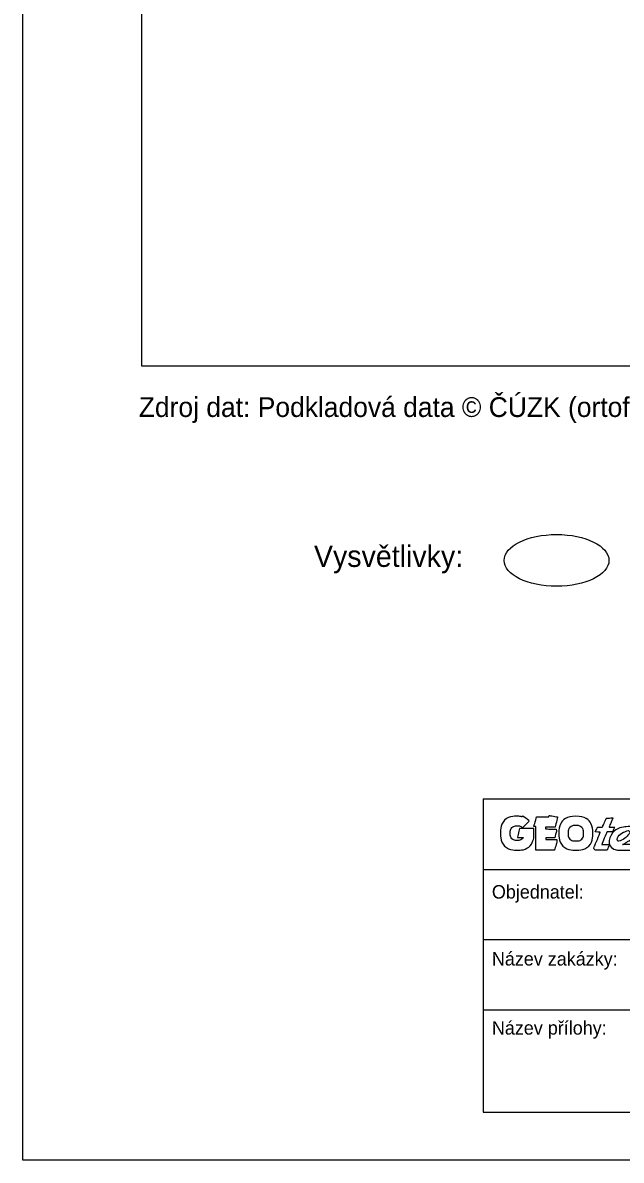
# Model space of a CAD drawing. Extents: x -600025 to -594775, y -1173009 to -1163890.
# Drawn here: x -600025 to -597810, y -1173009 to -1168801 of the extents above; entities that cross this region are included whole.
import ezdxf

# ---------------------------------------------------------------- set-up
doc = ezdxf.new("R2010")
doc.units = 0
doc.layers.add('razítko', color=7, linetype='Continuous')

msp = doc.modelspace()

# ---------------------------------------------------------------- linework, layer by layer
msp.add_lwpolyline([(-599584, -1165983.5), (-595112.9, -1165983.5), (-595112.9, -1170072.1), (-599584, -1170072.1)], close=True)
msp.add_ellipse((-598049.1, -1170790.4), major_axis=(193.8, 0), ratio=0.494798)
at = {"layer": 'razítko'}
for p, q in [((-598320.3, -1171672.8), (-598320.3, -1172831.8)), ((-598320.3, -1171673), (-595049.4, -1171673.3)), ((-598320.3, -1171673), (-595049.4, -1171673.3)), ((-598320.7, -1171933.3), (-595049.2, -1171933.5)), ((-598320.7, -1171933.3), (-595049.2, -1171933.5)), ((-598320.3, -1172193.1), (-595049.2, -1172193.4)), ((-598320.3, -1172193.1), (-595049.2, -1172193.4)), ((-598320.3, -1172453), (-595049.2, -1172453.2)), ((-598320.3, -1172453), (-595049.2, -1172453.2)), ((-598320.3, -1172832), (-595049.3, -1172832.3)), ((-598320.3, -1172832), (-595049.3, -1172832.3))]:
    msp.add_line(p, q, dxfattribs=at)
msp.add_lwpolyline([(-600024.6, -1165584.5), (-594774.6, -1165584.5), (-594774.6, -1173009.5), (-600024.6, -1173009.5)], close=True, dxfattribs=at)
for points in [[(-598150.1, -1171754.5), (-598150.1, -1171754.5), (-598175.1, -1171779.5), (-598175.1, -1171779.5), (-598175.1, -1171779.5), (-598180.1, -1171774.8), (-598186.8, -1171772.2), (-598193.7, -1171772.2), (-598193.7, -1171772.2), (-598208.6, -1171772.2), (-598220.8, -1171784.5), (-598220.8, -1171799.4), (-598220.8, -1171799.4), (-598220.8, -1171814.3), (-598208.6, -1171826.5), (-598193.7, -1171826.5), (-598193.7, -1171826.5), (-598184.8, -1171826.5), (-598176.6, -1171822.1), (-598171.6, -1171815), (-598171.6, -1171815), (-598171.6, -1171815), (-598193.3, -1171814.9), (-598193.3, -1171814.9), (-598193.3, -1171814.9), (-598193.3, -1171814.9), (-598186.4, -1171782), (-598186.4, -1171782), (-598186.4, -1171782), (-598186.4, -1171782), (-598132.7, -1171782.1), (-598132.7, -1171782.1), (-598132.7, -1171782.1), (-598132.7, -1171782.1), (-598132.8, -1171813.5), (-598132.8, -1171813.5), (-598132.8, -1171813.5), (-598139.2, -1171841.7), (-598164.6, -1171862), (-598193.7, -1171862), (-598193.7, -1171862), (-598228.2, -1171862), (-598256.3, -1171833.8), (-598256.3, -1171799.4), (-598256.3, -1171799.4), (-598256.3, -1171764.9), (-598228.2, -1171736.8), (-598193.7, -1171736.8), (-598193.7, -1171736.8), (-598188.3, -1171736.8), (-598182.7, -1171737.8), (-598177.5, -1171739), (-598177.5, -1171739), (-598177.5, -1171739), (-598174.8, -1171735.7), (-598174.8, -1171735.7), (-598174.8, -1171735.7), (-598174.8, -1171735.7), (-598150.1, -1171754.5), (-598150.1, -1171754.5)], [(-598125.5, -1171775.2), (-598125.5, -1171775.2), (-598125.5, -1171862.3), (-598125.5, -1171862.3), (-598125.5, -1171862.3), (-598125.5, -1171862.3), (-598056.6, -1171862.3), (-598056.6, -1171862.3), (-598056.6, -1171862.3), (-598056.6, -1171862.3), (-598047.9, -1171832.2), (-598047.9, -1171832.2), (-598047.9, -1171832.2), (-598047.9, -1171832.2), (-598047.9, -1171823.5), (-598047.9, -1171823.5), (-598047.9, -1171823.5), (-598047.9, -1171823.5), (-598089.1, -1171823.5), (-598089.1, -1171823.5), (-598089.1, -1171823.5), (-598089.1, -1171823.5), (-598089.1, -1171816.4), (-598089.1, -1171816.4), (-598089.1, -1171816.4), (-598089.1, -1171816.4), (-598055.8, -1171816.4), (-598055.8, -1171816.4), (-598055.8, -1171816.4), (-598055.8, -1171816.4), (-598049.5, -1171792.6), (-598049.5, -1171792.6), (-598049.5, -1171792.6), (-598049.5, -1171792.6), (-598050.3, -1171784.7), (-598050.3, -1171784.7), (-598050.3, -1171784.7), (-598050.3, -1171784.7), (-598089.9, -1171783.9), (-598089.9, -1171783.9), (-598089.9, -1171783.9), (-598089.9, -1171783.9), (-598089.9, -1171776.8), (-598089.9, -1171776.8), (-598089.9, -1171776.8), (-598089.9, -1171776.8), (-598054.2, -1171776.8), (-598054.2, -1171776.8), (-598054.2, -1171776.8), (-598054.2, -1171776.8), (-598045.5, -1171740.4), (-598045.5, -1171740.4), (-598045.5, -1171740.4), (-598045.5, -1171740.4), (-598045.5, -1171739.6), (-598045.5, -1171739.6), (-598045.5, -1171739.6), (-598045.5, -1171739.6), (-598076.4, -1171734), (-598076.4, -1171734), (-598076.4, -1171734), (-598076.4, -1171734), (-598078, -1171738.8), (-598078, -1171738.8), (-598078, -1171738.8), (-598078, -1171738.8), (-598123.1, -1171738.8), (-598123.1, -1171738.8), (-598123.1, -1171738.8), (-598123.1, -1171738.8), (-598133.4, -1171775.2), (-598133.4, -1171775.2), (-598133.4, -1171775.2), (-598133.4, -1171775.2), (-598125.5, -1171775.2), (-598125.5, -1171775.2)], [(-597977.8, -1171736.6), (-597943.2, -1171736.6), (-597915.1, -1171764.8), (-597915.1, -1171799.3), (-597915.1, -1171799.3), (-597915.1, -1171833.9), (-597943.2, -1171862.1), (-597977.8, -1171862.1), (-597977.8, -1171862.1), (-598012.3, -1171862.1), (-598040.5, -1171833.9), (-598040.5, -1171799.3), (-598040.5, -1171799.3), (-598040.5, -1171764.8), (-598012.3, -1171736.6), (-597977.8, -1171736.6)], [(-597853.8, -1171776.8), (-597853.8, -1171776.8), (-597855.4, -1171776.8), (-597853.8, -1171774.4), (-597853.8, -1171774.4), (-597853.8, -1171774.4), (-597841.1, -1171742.8), (-597841.1, -1171742.8), (-597841.1, -1171742.8), (-597841.1, -1171742.8), (-597864.9, -1171744.3), (-597864.9, -1171744.3), (-597864.9, -1171744.3), (-597864.9, -1171744.3), (-597877.6, -1171772.9), (-597877.6, -1171772.9), (-597877.6, -1171772.9), (-597879.2, -1171776.8), (-597881.5, -1171776.8), (-597882.3, -1171776.8), (-597882.3, -1171776.8), (-597882.3, -1171776.8), (-597897.4, -1171777.6), (-597897.4, -1171777.6), (-597897.4, -1171777.6), (-597897.4, -1171777.6), (-597906.1, -1171795), (-597906.1, -1171795), (-597906.1, -1171795), (-597906.1, -1171795), (-597887.9, -1171795.8), (-597887.9, -1171795.8), (-597887.9, -1171795.8), (-597887.9, -1171797.4), (-597888.7, -1171798.2), (-597888.7, -1171799), (-597888.7, -1171799), (-597888.7, -1171799), (-597907.7, -1171845.7), (-597907.7, -1171845.7), (-597907.7, -1171845.7), (-597912.4, -1171855.2), (-597906.9, -1171861.6), (-597902.1, -1171862.4), (-597902.1, -1171862.4), (-597902.1, -1171862.4), (-597862.5, -1171862.4), (-597862.5, -1171862.4), (-597862.5, -1171862.4), (-597862.5, -1171862.4), (-597853, -1171841), (-597853, -1171841), (-597853, -1171841), (-597853, -1171841), (-597881.5, -1171841), (-597881.5, -1171841), (-597881.5, -1171841), (-597881.5, -1171841), (-597882.3, -1171841), (-597880.8, -1171838.6), (-597880.8, -1171838.6), (-597880.8, -1171838.6), (-597864.1, -1171798.2), (-597864.1, -1171798.2), (-597864.1, -1171798.2), (-597862.5, -1171795), (-597862.5, -1171795), (-597861, -1171795), (-597861, -1171795), (-597861, -1171795), (-597842.7, -1171795), (-597842.7, -1171795), (-597842.7, -1171795), (-597842.7, -1171795), (-597834, -1171777.6), (-597834, -1171777.6), (-597834, -1171777.6), (-597834, -1171777.6), (-597853.8, -1171776.8), (-597853.8, -1171776.8)], [(-597977.8, -1171770.5), (-597961.9, -1171770.5), (-597948.9, -1171783.4), (-597948.9, -1171799.3), (-597948.9, -1171799.3), (-597948.9, -1171815.3), (-597961.9, -1171828.2), (-597977.8, -1171828.2), (-597977.8, -1171828.2), (-597993.7, -1171828.2), (-598006.6, -1171815.3), (-598006.6, -1171799.3), (-598006.6, -1171799.3), (-598006.6, -1171783.4), (-597993.7, -1171770.5), (-597977.8, -1171770.5)], [(-597824, -1171862.3), (-597864.8, -1171857.2), (-597850.3, -1171780.7), (-597779.4, -1171774.7), (-597779.4, -1171774.7), (-597730.9, -1171779.7), (-597774.3, -1171825.2), (-597788.6, -1171831.9), (-597788.6, -1171831.9), (-597794.8, -1171835.8), (-597796.5, -1171837), (-597801.9, -1171840.2), (-597801.9, -1171840.2), (-597804, -1171841.4), (-597805.3, -1171841.8), (-597804.1, -1171841.7), (-597804.1, -1171841.7), (-597802.2, -1171841.6), (-597803.8, -1171841.6), (-597799.8, -1171841.7), (-597799.8, -1171841.7), (-597799.8, -1171841.7), (-597738.9, -1171841.7), (-597738.9, -1171841.7), (-597738.9, -1171841.7), (-597718.8, -1171837.2), (-597717.9, -1171812), (-597724.4, -1171802.6), (-597724.4, -1171802.6), (-597724.9, -1171801.8), (-597725, -1171801.2), (-597726.3, -1171802.9), (-597726.3, -1171802.9), (-597726.3, -1171802.9), (-597737.7, -1171814.4), (-597737.7, -1171814.4), (-597737.7, -1171814.4), (-597737.7, -1171814.4), (-597759.8, -1171809), (-597759.8, -1171809), (-597759.8, -1171809), (-597759.8, -1171809), (-597715.3, -1171761.7), (-597715.3, -1171761.7), (-597715.3, -1171761.7), (-597715.3, -1171761.7), (-597689.5, -1171761.9), (-597689.5, -1171761.9), (-597689.5, -1171761.9), (-597689.5, -1171761.9), (-597706.1, -1171781.2), (-597706.1, -1171781.2), (-597706.1, -1171781.2), (-597706.5, -1171781.7), (-597707.6, -1171781.6), (-597705.7, -1171784.4), (-597705.7, -1171784.4), (-597684.6, -1171817.7), (-597704.8, -1171855.1), (-597731.9, -1171862.3), (-597731.9, -1171862.3), (-597731.9, -1171862.3), (-597824, -1171862.3), (-597824, -1171862.3)], [(-597822.3, -1171829), (-597812.4, -1171831.9), (-597774.3, -1171801.1), (-597780.2, -1171792), (-597780.2, -1171792), (-597786.2, -1171786.7), (-597831.9, -1171812.1), (-597822.3, -1171829)]]:
    msp.add_open_spline(points, degree=3, dxfattribs=at)

# ---------------------------------------------------------------- texts
for s, height, rotation, p in [('Zdroj dat: Podkladová data © ČÚZK (ortofoto); http://geoportal.cuzk.cz ', 73.125, 360, (-599595.3, -1170259.8)), ('Vysvětlivky:', 79.074, 360, (-598947, -1170814.5)), ('Objednatel:', 49.697, 359.9956, (-598288.5, -1172041.3)), ('Název zakázky:', 49.697, 359.9956, (-598288.5, -1172289.1)), ('Název přílohy:', 49.697, 359.9956, (-598288.5, -1172544.7))]:
    msp.add_text(s, height=height, rotation=rotation, dxfattribs=at).set_placement(p)

doc.saveas('drawing.dxf')
